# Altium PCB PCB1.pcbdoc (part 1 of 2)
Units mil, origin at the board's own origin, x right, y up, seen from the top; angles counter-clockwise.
Board outline 3270 x 3720 mil, 2 copper layers (Top Layer, Bottom Layer); 54 components, 39 nets, 206 pads, 56 vias.
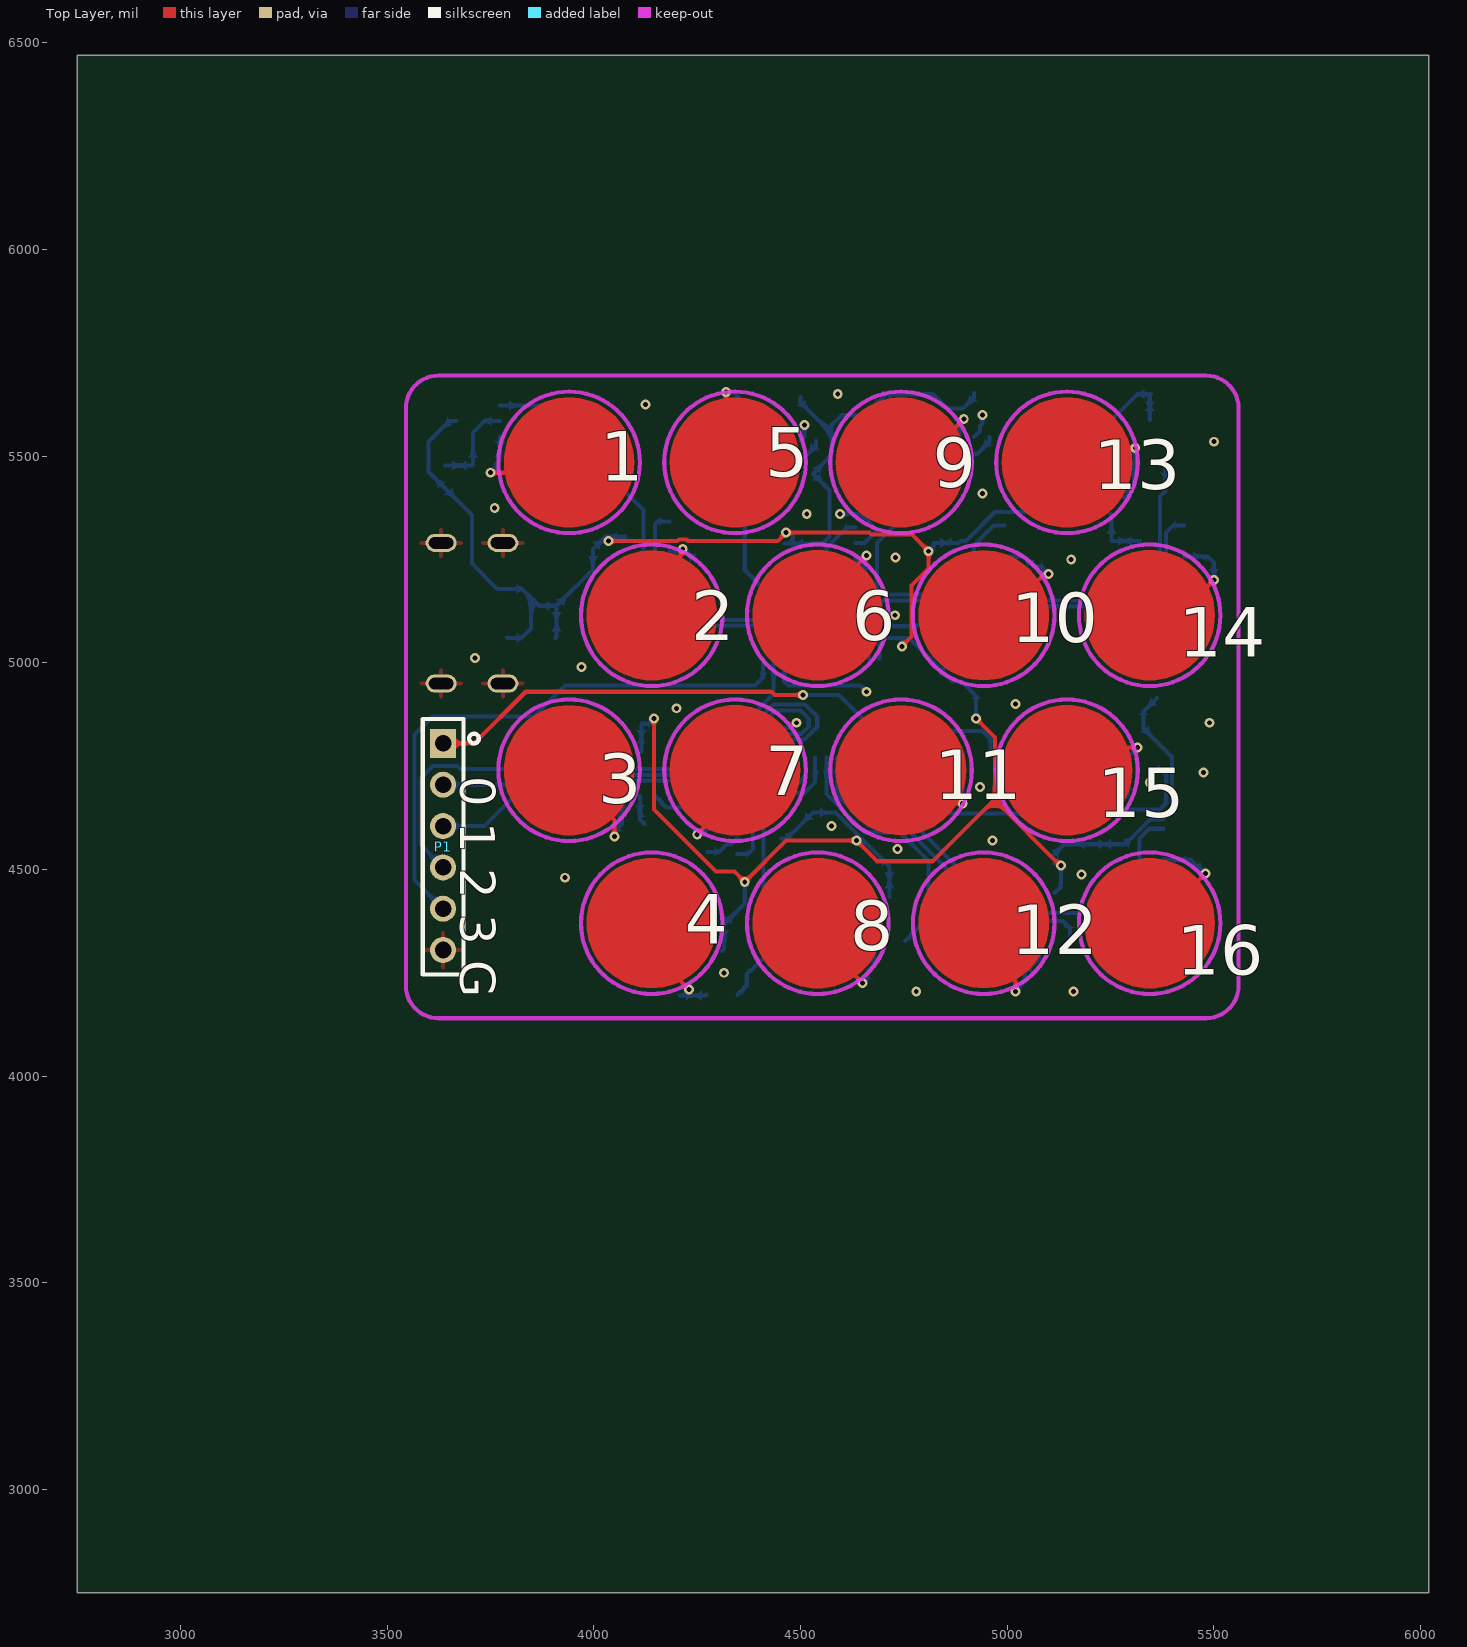
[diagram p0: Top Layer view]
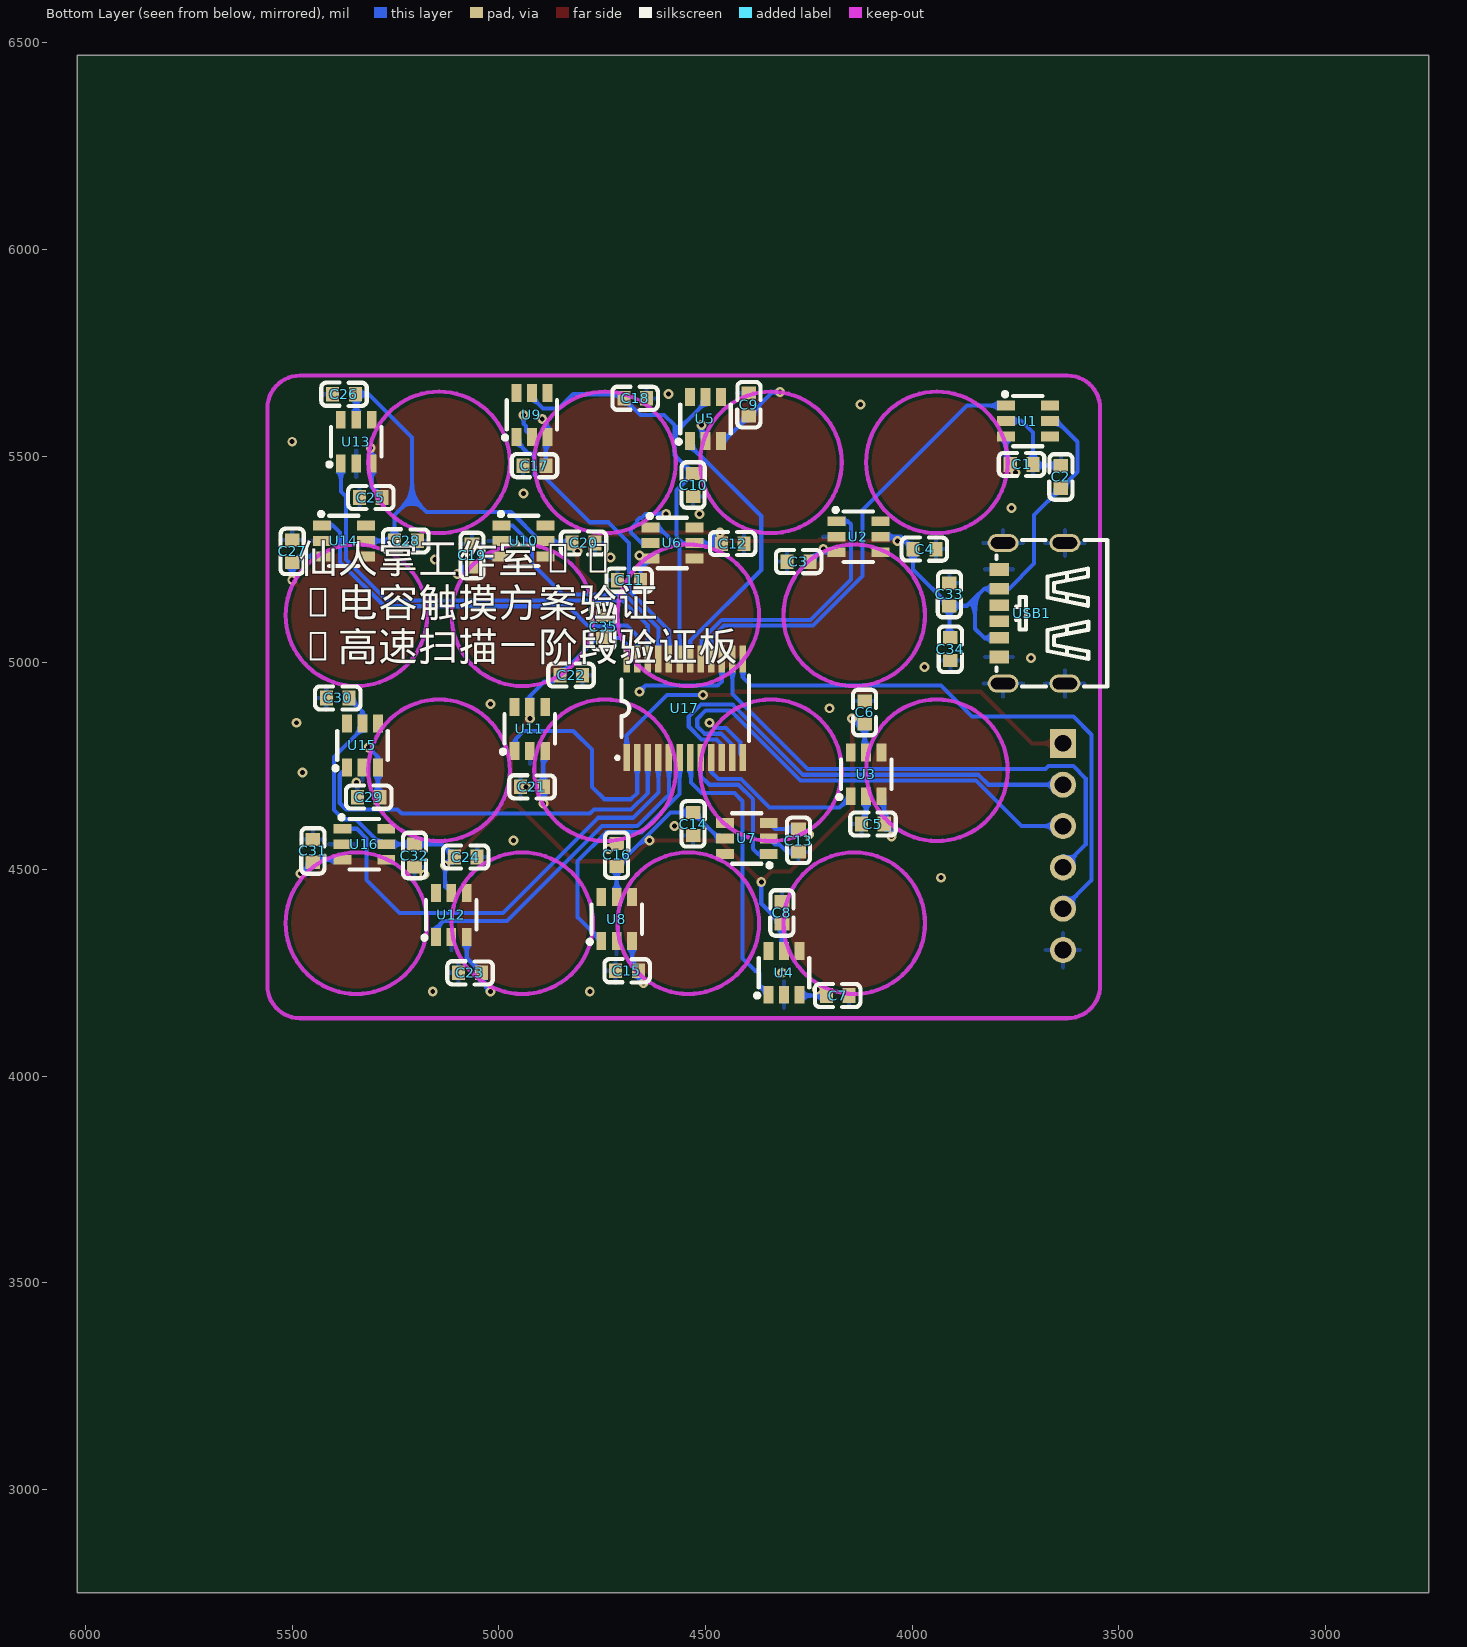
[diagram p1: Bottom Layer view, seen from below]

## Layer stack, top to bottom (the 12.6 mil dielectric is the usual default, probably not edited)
Top Layer: signal copper (thickness not stored)
Dielectric: dielectric 12.6, FR-4, Dk 4.8
Bottom Layer: signal copper (thickness not stored)

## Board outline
6020,2750 2750,2750 2750,6470 6020,6470

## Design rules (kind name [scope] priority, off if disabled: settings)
Clearance copperThickness1oz [All] p1: gap=7 ignorepadtopadclearanceinfootprint=FALSE except(4: Track-Track; 6: Track-SMDPad SMDPad-SMDPad Track-THPad SMDPad-THPad THPad-THPad Track-Via SMDPad-Via THPad-Via Via-Via SMDPad-Fill THPad-Fill Via-Fill Fill-Fill Track-Region SMDPad-Region THPad-Region Via-Region Region-Region Track-Poly SMDPad-Poly THPad-Poly Via-Poly Fill-Poly Region-Poly Poly-Poly Track-Text SMDPad-Text THPad-Text Via-Text Fill-Text Region-Text Poly-Text Text-Text; 6.9: Track-Hole SMDPad-Hole THPad-Hole Via-Hole Fill-Hole Region-Hole Poly-Hole Text-Hole Sheet-Hole; 11.8: Track-Fill Fill-Region Track-Sheet SMDPad-Sheet THPad-Sheet Via-Sheet Fill-Sheet Region-Sheet Poly-Sheet Text-Sheet)
Clearance copperThickness2oz [All] p1: gap=7 ignorepadtopadclearanceinfootprint=FALSE except(6: Track-SMDPad SMDPad-SMDPad Track-THPad SMDPad-THPad THPad-THPad Track-Via SMDPad-Via THPad-Via Via-Via SMDPad-Fill THPad-Fill Via-Fill Fill-Fill Track-Region SMDPad-Region THPad-Region Via-Region Region-Region Track-Poly SMDPad-Poly THPad-Poly Via-Poly Fill-Poly Region-Poly Poly-Poly Track-Text SMDPad-Text THPad-Text Via-Text Fill-Text Region-Text Poly-Text Text-Text; 6.9: Track-Hole SMDPad-Hole THPad-Hole Via-Hole Fill-Hole Region-Hole Poly-Hole Text-Hole Sheet-Hole; 8: Track-Track; 11.8: Track-Fill Fill-Region Track-Sheet SMDPad-Sheet THPad-Sheet Via-Sheet Fill-Sheet Region-Sheet Poly-Sheet Text-Sheet)
DiffPairsRouting differentialPair [All] p1: maxuncoupledlength=10 maxlimit=6 mostfreqgap=6 toplayer_minwidth=5 toplayer_prefwidth=10 toplayer_maxwidth=100 bottomlayer_minwidth=5 bottomlayer_prefwidth=10 bottomlayer_maxwidth=100
PasteMaskExpansion pasteMaskExpansion [All] p1:
PlaneConnect innerPlane [All] p1: planeconnectstyle=Relief reliefexpansion=20 reliefentries=4 reliefconductorwidth=10 reliefairgap=10
PolygonConnect copperRegion [All] p1: connectstyle=Relief reliefentries=4 reliefconductorwidth=10 polygonreliefangle="90 Angle" airgapwidth=10
RoutingVias viaSize [All] p1: viastyle="Through Hole" holewidth=12.0078 minholewidth=11.811 maxholewidth=248.0314 width=24.0158 minwidth=19.685 maxwidth=393.7008
SolderMaskExpansion solderMaskExpansion [All] p1: useseparateexpansions=TRUE expansion=2 expansionbottom=2
Width copperThickness1oz [All] p1: maxlimit=100 minlimit=5 preferedwidth=10
Width copperThickness2oz [All] p1: maxlimit=100 minlimit=8 preferedwidth=10

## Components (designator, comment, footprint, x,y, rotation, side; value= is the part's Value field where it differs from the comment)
C1 "CL10C120JB8NNNC" C0603 3735,5480 r180 bottom
C2 "CC0603KRX7R9BB104" C0603 3640,5450 r90 bottom
C3 "CL10C120JB8NNNC" C0603 4275,5245 r0 bottom
C4 "CC0603KRX7R9BB104" C0603 3970,5275 r180 bottom
C5 "CL10C120JB8NNNC" C0603 4095,4610 r0 bottom
C6 "CC0603KRX7R9BB104" C0603 4115,4880 r90 bottom
C7 "CL10C120JB8NNNC" C0603 4180,4195 r180 bottom
C8 "CC0603KRX7R9BB104" C0603 4315,4395 r90 bottom
C9 "CL10C120JB8NNNC" C0603 4395,5625 r90 bottom
C10 "CC0603KRX7R9BB104" C0603 4530,5430 r270 bottom
C11 "CL10C120JB8NNNC" C0603 4685,5200 r0 bottom
C12 "CC0603KRX7R9BB104" C0603 4434.1,5288.47 r180 bottom
C13 "CL10C120JB8NNNC" C0603 4275,4570 r270 bottom
C14 "CC0603KRX7R9BB104" C0603 4530,4610 r270 bottom
C15 "CL10C120JB8NNNC" C0603 4690,4255 r0 bottom
C16 "CC0603KRX7R9BB104" C0603 4715,4535 r90 bottom
C17 "CL10C120JB8NNNC" C0603 4913.96,5477.13 r0 bottom
C18 "CC0603KRX7R9BB104" C0603 4670,5640 r180 bottom
C19 "CL10C120JB8NNNC" C0603 5065,5260 r90 bottom
C20 "CC0603KRX7R9BB104" C0603 4795,5290 r180 bottom
C21 "CL10C120JB8NNNC" C0603 4920,4700 r0 bottom
C22 "CC0603KRX7R9BB104" C0603 4825,4970 r180 bottom
C23 "CL10C120JB8NNNC" C0603 5070,4250 r0 bottom
C24 "CC0603KRX7R9BB104" C0603 5080,4530 r180 bottom
C25 "CL10C120JB8NNNC" C0603 5310,5400 r0 bottom
C26 "CC0603KRX7R9BB104" C0603 5375,5650 r0 bottom
C27 "CL10C120JB8NNNC" C0603 5500,5270 r90 bottom
C28 "CC0603KRX7R9BB104" C0603 5225,5295 r180 bottom
C29 "CL10C120JB8NNNC" C0603 5315,4675 r0 bottom
C30 "CC0603KRX7R9BB104" C0603 5390,4915 r0 bottom
C31 "CL10C120JB8NNNC" C0603 5450,4545 r90 bottom
C32 "CC0603KRX7R9BB104" C0603 5204.22,4533.59 r270 bottom
C33 "CC0603KRX7R9BB104" C0603 3909.79,5165.61 r90 bottom
C34 "CL10A106KP8NNNC" C0603 3907.35,5033.17 r90 bottom
C35 "CC0603KRX7R9BB104" C0603 4747.62,5087.54 r90 bottom
P1 "2.54-1*6P母" hdr-th_6p-p2.54-v-f 3635,4555 r270 top
U1 "TTP223E-HA6" SOT-23-6_L2.9-W1.6-P0.95-LS2.8-BR 3720,5585 r0 bottom
U2 "TTP223E-HA6" SOT-23-6_L2.9-W1.6-P0.95-LS2.8-BR 4130,5305 r0 bottom
U3 "TTP223E-HA6" SOT-23-6_L2.9-W1.6-P0.95-LS2.8-BR 4111.3,4730.21 r270 bottom
U4 "TTP223E-HA6" SOT-23-6_L2.9-W1.6-P0.95-LS2.8-BR 4310,4250 r270 bottom
U5 "TTP223E-HA6" SOT-23-6_L2.9-W1.6-P0.95-LS2.8-BR 4500,5590 r270 bottom
U6 "TTP223E-HA6" SOT-23-6_L2.9-W1.6-P0.95-LS2.8-BR 4580,5290 r0 bottom
U7 "TTP223E-HA6" SOT-23-6_L2.9-W1.6-P0.95-LS2.8-BR 4400,4575 r180 bottom
U8 "TTP223E-HA6" SOT-23-6_L2.9-W1.6-P0.95-LS2.8-BR 4715,4380 r270 bottom
U9 "TTP223E-HA6" SOT-23-6_L2.9-W1.6-P0.95-LS2.8-BR 4920,5600 r270 bottom
U10 "TTP223E-HA6" SOT-23-6_L2.9-W1.6-P0.95-LS2.8-BR 4940,5295 r0 bottom
U11 "TTP223E-HA6" SOT-23-6_L2.9-W1.6-P0.95-LS2.8-BR 4925,4840 r270 bottom
U12 "TTP223E-HA6" SOT-23-6_L2.9-W1.6-P0.95-LS2.8-BR 5115,4390 r270 bottom
U13 "TTP223E-HA6" SOT-23-6_L2.9-W1.6-P0.95-LS2.8-BR 5345,5535 r270 bottom
U14 "TTP223E-HA6" SOT-23-6_L2.9-W1.6-P0.95-LS2.8-BR 5375,5295 r0 bottom
U15 "TTP223E-HA6" SOT-23-6_L2.9-W1.6-P0.95-LS2.8-BR 5330,4800 r270 bottom
U16 "TTP223E-HA6" SOT-23-6_L2.9-W1.6-P0.95-LS2.8-BR 5325.54,4561.15 r0 bottom
U17 "74HC4067PW/C2118" TSSOP-24_L7.8-W4.4-P0.65-LS6.4-BL 4550,4890 r180 bottom
USB1 "TYPE-C 6P" TYPE-C-SMD_TYPE-C-6P 3710,5120 r90 bottom

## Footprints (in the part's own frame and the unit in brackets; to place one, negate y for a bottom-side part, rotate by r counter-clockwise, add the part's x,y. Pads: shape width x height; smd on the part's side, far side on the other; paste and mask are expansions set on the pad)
C0603 [mm]
  rect 0.8x0.9 smd: 1(-0.7,0) 2(0.7,0)
  silkscreen extent -1.41,-0.71 1.39,0.72
hdr-th_6p-p2.54-v-f [mm]
  rect 1.8x1.6 hole 1.02: 1(-6.35,0)
  round 1.6 hole 1.02: 2(-3.81,0) 3(-1.27,0) 4(1.27,0) 5(3.81,0) 6(6.35,0)
  silkscreen extent -7.85,-1.25 7.85,2.2
SOT-23-6_L2.9-W1.6-P0.95-LS2.8-BR [mm]
  rect 1.1x0.6 smd: 1(1.35,-0.95) 2(1.35,0) 3(1.35,0.95) 4(-1.35,0.95) 5(-1.35,0) 6(-1.35,-0.95)
  silkscreen extent -0.9,-1.78 1.52,1.55
TSSOP-24_L7.8-W4.4-P0.65-LS6.4-BL [mm]
  rect 0.4x1.65 smd: 1(-3.575,-3.023) 2(-2.925,-3.023) 3(-2.275,-3.023) 4(-1.625,-3.023) 5(-0.975,-3.023) 6(-0.325,-3.023) 7(0.325,-3.023) 8(0.975,-3.023) 9(1.625,-3.023) 10(2.275,-3.023) 11(2.925,-3.023) 12(3.575,-3.023) 13(3.575,3.023) 14(2.925,3.023) 15(2.275,3.023) 16(1.625,3.023) 17(0.975,3.023) 18(0.325,3.023) 19(-0.325,3.023) 20(-0.975,3.023) 21(-1.625,3.023) 22(-2.275,3.023) 23(-2.925,3.023) 24(-3.575,3.023)
  silkscreen extent -4.24,-3.15 3.94,2.01
TYPE-C-SMD_TYPE-C-6P [mm]
  oval 1.1x1.9 hole 0.7 slot 1.5 at 90 deg: 7(-4.32,-2.025) 7(-4.32,1.775) 7(4.32,-2.025) 7(4.32,1.775)
  rect 0.7x1.2 smd: A5(-0.5,2.025) A9(1.5,2.025) B5(0.5,2.025) B9(-1.5,2.025)
  rect 0.8x1.2 smd: A12(2.7,2.025) B12(-2.7,2.025)
  silkscreen extent -4.5,-4.63 4.5,2.18

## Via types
v1: diameter 24.02, hole 12.01, Top Layer to Bottom Layer, 56 vias

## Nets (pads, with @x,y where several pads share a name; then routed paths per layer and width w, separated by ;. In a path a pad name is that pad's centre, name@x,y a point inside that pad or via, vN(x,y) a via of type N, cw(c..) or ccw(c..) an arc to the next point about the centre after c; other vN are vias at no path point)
+5V: C2.1 C4.1 C6.1 C8.1 C10.1 C12.1 C14.1 C16.1 C18.1 C20.1 C22.1 C24.1 C26.1 C28.1 C30.1 C32.1 C33.1 C34.2 C35.1 U1.5 U2.5 U3.5 U4.5 U5.5 U6.5 U7.5 U8.5 U9.5 U10.5 U11.5 U12.5 U13.5 U14.5 U15.5 U16.5 U17.24 USB1.A9 USB1.B9 | length 7845.7
  Top Layer w10: v1(4035,5295) 4202.48,5295 4205.48,5297.99 4224.52,5297.99 4227.52,5295 4445,5295 v1(4465,5315) 4666.66,5315 4670.96,5310.71 4769.29,5310.71 v1(4810,5270) 4810,5228.34 4768.86,5187.19 4768.86,5063.86 v1(4745,5040) ; v1(4145,4865) 4145,4645 4295,4495 4340,4495 v1(4365,4470) 4465,4570 v1(4635,4570) 4685,4520 4820,4520 4967.81,4667.81 4970.43,4667.81 ; v1(4925,4865) 4970.43,4819.57 4970.43,4667.81 ; v1(5130,4510) 5128.24,4510 4970.43,4667.81
  Bottom Layer w10: U1.5@3666.85,5585 3650,5585 3600,5535 3600,5462.44 C2.1@3640,5422.44 3705,5357.44 3705,5240 3765.95,5179.06 USB1.A9@3789.72,5179.06 3825.95,5179.06 3847.5,5157.5 ; USB1.B9@3789.72,5060.94 3790.67,5060 3825,5060 3847.5,5082.5 3847.5,5157.5 ; C34.2@3907.35,5060.73 3909.79,5063.17 C33.1@3909.79,5138.05 ; v1(4035,5295) 4035,5297.56 4027.56,5305 ; U2.5@4076.85,5305 4027.56,5305 ; U3.5@4111.3,4783.36 4115,4787.07 C6.1@4115,4852.44 4132.44,4852.44 v1(4145,4865) ; U4.5@4310,4303.15 4315,4308.15 C8.1@4315,4367.44 4365,4417.44 v1(4365,4470) ; U7.5@4453.15,4575 4467.44,4575 C14.1@4530,4637.56 4584.88,4637.56 4652.44,4570 ; C12.1@4461.66,5288.47 C12.1@4471.72,5288.47 ; v1(4465,5315) 4474.74,5315 4481.62,5308.11 4481.62,5298.38 C12.1@4471.72,5288.47 ; U5.5@4500,5643.15 4500,5630 4575,5555 ; v1(4635,4570) 4652.44,4570 ; U17.24@4690.74,5009 4690.74,5045.74 4704.98,5059.98 C35.1@4747.62,5059.98 ; U8.5@4715,4433.15 C16.1@4715,4507.44 4652.44,4570 ; v1(4745,5040) 4745,5057.36 C35.1@4747.62,5059.98 ; v1(4810,5270) 4822.56,5282.56 C20.1@4822.56,5290 4881.85,5290 U10.5@4886.85,5295 4900,5295 4970,5365 5175,5365 5210,5400 ; U9.5@4920,5653.15 4920,5641.55 4893.45,5615 4855,5615 4820,5650 4707.56,5650 C18.1@4697.56,5640 4657.56,5600 4600,5600 4575,5575 4575,5555 ; v1(4925,4865) U11.5@4925,4893.15 4925,4920 4890,4955 4867.56,4955 C22.1@4852.56,4970 4762.58,5059.98 C35.1@4747.62,5059.98 ; U12.5@5115,4443.15 5129.6,4457.75 5129.6,4469.35 5130,4469.75 v1(5130,4510) 5127.56,4510 C24.1@5107.56,4530 5138.71,4561.15 C32.1@5204.22,4561.15 U16.5@5272.39,4561.15 5286.15,4561.15 5345.98,4620.98 5352.12,4620.98 5352.48,4621.35 5376.35,4621.35 5399.02,4644.02 5399.02,4772.54 5330,4841.55 U15.5@5330,4853.15 5330,4882.56 C30.1@5362.44,4915 ; U14.5@5321.85,5295 C28.1@5252.56,5295 5252.56,5357.44 5210,5400 ; U13.5@5345,5588.15 5345,5647.56 C26.1@5347.44,5650 5315,5650 5210,5545 5210,5400 ; 3847.5,5157.5 3866.95,5138.05 C33.1@3909.79,5138.05 ; C33.1@3909.79,5138.05 3997.56,5225.82 C4.1@3997.56,5275 4027.56,5305 ; C12.1@4471.72,5288.47 4525.32,5288.47 U6.5@4526.85,5290 4555,5290 4570,5305 4570,5417.56 C10.1@4530,5457.56 4575,5502.56 4575,5555
GND: C1.2 C2.2 C3.2 C4.2 C5.2 C6.2 C7.2 C8.2 C9.2 C10.2 C11.2 C12.2 C13.2 C14.2 C15.2 C16.2 C17.2 C18.2 C19.2 C20.2 C21.2 C22.2 C23.2 C24.2 C25.2 C26.2 C27.2 C28.2 C29.2 C30.2 C31.2 C32.2 C33.2 C34.1 C35.2 P1.6 U1.2 U2.2 U3.2 U4.2 U5.2 U6.2 U7.2 U8.2 U9.2 U10.2 U11.2 U12.2 U13.2 U14.2 U15.2 U16.2 U17.12 U17.15 USB1.7 USB1.A12 USB1.B12 | length 1050.4
  Bottom Layer w10: C2.2@3640,5477.56 3705,5477.56 C1.2@3707.44,5480 3707.44,5557.44 3735,5585 U1.2@3773.15,5585 ; U3.2@4111.3,4677.06 4111.3,4621.27 C5.2@4122.56,4610 ; C13.2@4275,4542.44 4302.69,4542.44 4320.65,4560.4 4332.25,4560.4 U7.2@4346.85,4575 ; U17.12@4409.26,4771 4409.26,4774.26 4415.98,4780.98 4415.98,4808.03 4450.45,4842.5 4477.5,4842.5 v1(4490,4855) ; U17.15@4460.43,5009 4460.43,4955 4470.43,4945 4645,4945 v1(4660,4930) ; U5.2@4500,5536.85 4510,5546.85 v1(4510,5575) ; v1(4595,5360) 4645,5360 4654.8,5350.2 4659.35,5350.2 4665.79,5343.76 4665.79,5339.21 4680,5325 4680,5315 4655,5290 U6.2@4633.15,5290 ; U9.2@4920,5546.85 4934.6,5561.45 4934.6,5573.05 4940,5578.45 v1(4940,5600)
  other v1: 4780,4205 5160,4205 4314.49,4250 3930,4480 5179.86,4487.49 4735,4550 4965,4570 4575,4605 4933.97,4699.89 5345,4710 5475,4735 5490,4855 4200,4890 5020,4900 3970,4990 3712.13,5011.73 4728.52,5115.1 5155,5250 4730,5255 4515,5360 3760,5375 4940,5410 5500,5535 4125,5625 4590,5650
OUT: P1.1 U17.1 | length 1204.6
  Top Layer w10: P1.1@3635,4805 3710,4805 3835,4930 4430,4930 4437.99,4922.01 v1(4506.26,4922.01)
  Bottom Layer w10: v1(4506.26,4922.01) 4592.99,4922.01 4690.74,4824.26 U17.1@4690.74,4771
PAD1: 
PAD2: C3.1 U2.3 | length 122.4
  Top Layer w10: 4195,5245 4215,5265 v1(4215,5275)
  Bottom Layer w10: U2.3@4183.15,5267.6 v1@4207.6,5267.6 ; v1(4215,5275) v1@4207.6,5267.6 ; C3.1@4247.44,5245 4224.84,5267.6 v1@4207.6,5267.6
PAD3: C5.1 U3.3 | length 168.2
  Top Layer w10: 4035,4635 4050,4620 v1(4050,4580)
  Bottom Layer w10: v1(4050,4580) 4050,4592.56 C5.1@4067.44,4610 4067.44,4670.61 U3.3@4073.89,4677.06
PAD4: C7.1 U4.3 | length 160.7
  Top Layer w10: 4185,4265 4185,4255 v1(4230,4210)
  Bottom Layer w10: C7.1@4207.56,4195 C7.1@4215,4195 ; v1(4230,4210) C7.1@4215,4195 ; U4.3@4272.6,4196.85 4270.75,4195 C7.1@4215,4195
PAD5: C9.1 U5.3 | length 263.1
  Top Layer w10: v1(4320,5655) 4320,5640 4360,5600
  Bottom Layer w10: v1(4320,5655) 4337.44,5655 C9.1@4395,5597.44 4455.59,5536.85 U5.3@4462.6,5536.85
PAD6: C11.1 U6.3 | length 142.9
  Top Layer w10: 4635,5220 4635,5235 v1(4660,5260)
  Bottom Layer w10: C11.1@4657.44,5200 4657.44,5228.31 U6.3@4633.15,5252.6 4652.6,5252.6 v1(4660,5260)
PAD7: C13.1 U7.3 | length 158.6
  Top Layer w10: v1(4250,4585) 4275,4610 4275,4625
  Bottom Layer w10: v1(4250,4585) 4262.44,4585 C13.1@4275,4597.56 4320.41,4597.56 4320.65,4597.8 4332.25,4597.8 U7.3@4346.85,4612.4
PAD8: C15.1 U8.3 | length 218.1
  Top Layer w10: 4590,4305 4590,4285 v1(4650,4225)
  Bottom Layer w10: v1(4650,4225) 4662.44,4237.44 C15.1@4662.44,4255 4677.6,4270.16 U8.3@4677.6,4326.85
PAD9: C17.1 U9.3 | length 169.1
  Top Layer w10: 4860,5555 v1(4895,5590)
  Bottom Layer w10: C17.1@4886.4,5477.13 4886.4,5543.05 U9.3@4882.6,5546.85 4885,5549.25 4885,5580 v1(4895,5590)
PAD10: C19.1 U10.3 | length 205.2
  Top Layer w10: 5040,5165 5090,5215 v1(5100,5215)
  Bottom Layer w10: U10.3@4993.15,5257.6 5039.84,5257.6 C19.1@5065,5232.44 5082.56,5232.44 v1(5100,5215)
PAD11: C21.1 U11.3 | length 205.8
  Top Layer w10: 4830,4695 4865,4660 v1(4892.44,4660)
  Bottom Layer w10: U11.3@4887.6,4786.85 4892.44,4782.01 C21.1@4892.44,4700 v1(4892.44,4660)
PAD12: C23.1 U12.3 | length 230.2
  Top Layer w10: 4985,4265 5020,4230 v1(5020,4205)
  Bottom Layer w10: v1(5020,4205) 5042.44,4227.44 C23.1@5042.44,4250 5077.6,4285.16 U12.3@5077.6,4336.85
PAD13: C25.1 U13.3 | length 234.7
  Top Layer w10: 5215,5500 5235,5520 v1(5310,5520)
  Bottom Layer w10: C25.1@5282.44,5400 5307.6,5425.16 U13.3@5307.6,5481.85 5310,5484.25 v1(5310,5520)
PAD14: C27.1 U14.3 | length 191.8
  Top Layer w10: 5435,5185 5485,5185 v1(5500,5200)
  Bottom Layer w10: U14.3@5428.15,5257.6 5484.84,5257.6 C27.1@5500,5242.44 v1(5500,5200)
PAD15: C29.1 U15.3 | length 251.8
  Top Layer w10: 5205,4770 5230,4795 v1(5315,4795)
  Bottom Layer w10: C29.1@5287.44,4675 5292.6,4680.16 U15.3@5292.6,4746.85 5292.6,4772.6 v1(5315,4795)
PAD16: C31.1 U16.3 | length 157.7
  Top Layer w10: 5450,4460 v1(5480,4490)
  Bottom Layer w10: U16.3@5378.69,4523.75 5443.69,4523.75 C31.1@5450,4517.44 5477.44,4490 v1(5480,4490)
S0: P1.2 U17.10 | length 1150.7
  Bottom Layer w10: P1.2@3635,4705 3815.18,4705 3839.19,4729.02 4264.19,4729.02 4434.19,4899.02 4510.98,4899.02 4540.37,4869.63 4540.37,4845.37 4509.46,4814.46 4473.6,4814.46 4460.43,4801.3 U17.10@4460.43,4771
S1: P1.3 U17.11 | length 1162
  Bottom Layer w10: P1.3@3635,4605 3735,4605 3845,4715 4270,4715 4440,4885 4499.5,4885 4520,4864.5 4520,4845.93 4502.55,4828.48 4462.02,4828.48 4434.84,4801.3 U17.11@4434.84,4771
S2: P1.4 U17.14 | length 1267.4
  Bottom Layer w10: P1.4@3635,4505 3580,4560 3580,4720 3610,4750 3670,4750 3676.97,4743.03 4253.03,4743.03 4434.84,4924.84 U17.14@4434.84,5009
S3: P1.5 U17.13 | length 1394.9
  Bottom Layer w10: P1.5@3635,4405 3565.98,4474.02 3565.98,4825.98 3610,4870 3855,4870 3930,4945 4390,4945 4409.26,4964.26 U17.13@4409.26,5009
T1: U1.1 U17.16 | length 1090
  Bottom Layer w10: U1.1@3773.15,5622.4 3867.6,5622.4 4120,5370 4120,5210 4240,5090 4455,5090 4486.02,5058.98 U17.16@4486.02,5009
T2: U2.1 U17.17 | length 641.1
  Bottom Layer w10: U2.1@4183.15,5342.4 4155,5342.4 4147.93,5335.33 4147.93,5201.89 4245.81,5104.02 4460.81,5104.02 4509.82,5055 4509.82,5010.79 U17.17@4511.61,5009
T3: U3.1 U17.9 | length 419.1
  Bottom Layer w10: U3.1@4148.69,4677.06 4175.76,4650 4345.18,4650 4414.19,4719.02 4469.02,4719.02 4486.02,4736.02 U17.9@4486.02,4771
T4: U4.1 U17.7 | length 700.4
  Bottom Layer w10: U4.1@4347.4,4196.85 4370,4219.45 4370,4247.93 4377.07,4255 4380,4255 4410,4285 4410,4665 4430,4685 4510,4685 4535,4710 U17.7@4535,4771
T5: U5.1 U17.18 | length 671.9
  Bottom Layer w10: U17.18@4537.21,5009 4537.21,5052.79 4365,5225 4365,5355 4514.21,5504.21 4516.36,5504.21 4537.4,5525.25 U5.1@4537.4,5536.85
T6: U6.1 U17.19 | length 359.8
  Bottom Layer w10: U17.19@4562.79,5009 4562.79,5277.97 4612.22,5327.4 U6.1@4633.15,5327.4
T7: U7.1 U17.8 | length 357.7
  Bottom Layer w10: U7.1@4346.85,4537.6 4372.6,4537.6 4385,4550 4385,4670 4420,4705 4490,4705 4511.61,4726.61 U17.8@4511.61,4771
T8: U8.1 U17.6 | length 620.2
  Bottom Layer w10: U17.6@4562.79,4771 4562.79,4682.21 4655,4590 4740,4590 4810,4520 4810,4384.45 U8.1@4752.4,4326.85
T9: U9.1 U17.20 | length 731.7
  Bottom Layer w10: U17.20@4588.38,5009 4588.38,5078.38 4685,5175 4685,5290 4735,5340 4779.79,5340 4888.22,5448.43 4906.7,5448.43 4913.13,5454.86 4913.13,5473.34 4914.79,5475 4914.79,5499.4 4921.22,5505.83 4927.98,5505.83 4957.4,5535.25 U9.1@4957.4,5546.85
T10: U10.1 U17.21 | length 583.9
  Bottom Layer w10: U17.21@4613.97,5009 4613.97,5084.15 4694.82,5165 4845,5165 4920,5240 4920,5250 4919.49,5250.51 4919.49,5284.49 4967.4,5332.4 U10.1@4993.15,5332.4
T11: U11.1 U17.2 | length 545.7
  Bottom Layer w10: U17.2@4665,4771 4665,4685 4680,4670 4745,4670 4775,4700 4775,4790 4820,4835 4940,4835 4960,4815 4960,4789.25 U11.1@4962.4,4786.85
T12: U12.1 U17.5 | length 808.4
  Bottom Layer w10: U17.5@4588.38,4771 4588.38,4681.62 4665,4605 4750,4605 4980,4375 5135,4375 5152.4,4357.6 U12.1@5152.4,4336.85
T13: U13.1 U17.22 | length 1114.7
  Bottom Layer w10: U17.22@4639.56,5009 4639.56,5089.92 4700.63,5150.98 5270.98,5150.98 5370,5250 5370,5402.06 5382.4,5414.46 U13.1@5382.4,5481.85
T14: U14.1 U17.23 | length 972.8
  Bottom Layer w10: U17.23@4665.15,5009 4665.15,5054.85 4665,5055 4665,5065 4690,5090 4723.72,5090 4725.35,5088.37 4769.88,5088.37 4771.51,5090 4785,5090 4831.97,5136.97 5276.79,5136.97 5384.02,5244.19 5384.02,5315 5401.42,5332.4 U14.1@5428.15,5332.4
T15: U15.1 U17.3 | length 956
  Bottom Layer w10: U17.3@4639.56,4771 4639.56,4685.44 4680,4645 4770,4645 4780,4635 5235,4635 5245,4645 5369.27,4645 5385,4660.73 5385,4729.25 U15.1@5367.4,4746.85
T16: U16.1 U17.4 | length 1113.1
  Bottom Layer w10: U17.4@4613.97,4771 4613.97,4686.03 4675,4625 4760,4625 4990,4395 5240,4395 5320,4475 5320,4575 5343.55,4598.55 U16.1@5378.69,4598.55
pads on no net: C1.1 U1.3 U1.4 U1.6 U2.4 U2.6 U3.4 U3.6 U4.4 U4.6 U5.4 U5.6 U6.4 U6.6 U7.4 U7.6 U8.4 U8.6 U9.4 U9.6 U10.4 U10.6 U11.4 U11.6 U12.4 U12.6 U13.4 U13.6 U14.4 U14.6 U15.4 U15.6 U16.4 U16.6 USB1.A5 USB1.B5
copper on no net: | length 142.2
  Top Layer w10: v1(3750,5460) 3795,5460
  Bottom Layer w10: v1(3750,5460) 3762.56,5472.56 3762.56,5480 3773.15,5490.59 3773.15,5547.6

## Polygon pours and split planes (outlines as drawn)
GND on Bottom Layer (solid, remove dead copper, pour order 2): 3345,3900 5770,3900 5770,5870 3345,5870
GND on Top Layer (solid, remove dead copper): 3000,3000 5635,3000 5635,6220 3000,6220

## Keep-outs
Board Outline Layer:
  lines w10: 3545,4218.74 ccw(c3623.74,4218.74) 3623.74,4140 5481.26,4140 ccw(c5481.26,4218.74) 5560,4218.74 5560,5616.26 ccw(c5481.26,5616.26) 5481.26,5695 3623.74,5695 ccw(c3623.74,5616.26) 3545,5616.26 3545,4218.74
Multi-Layer:
  circle w10: c3940,5485 r171.26
  circle w10: c4341.57,5485 r171.26
  circle w10: c4140,5115 r171.26
  circle w10: c3940,4740 r171.26
  circle w10: c4341.57,4740 r171.26
  circle w10: c4140,4370 r171.26
  circle w10: c4541.57,4370 r171.26
  circle w10: c4943.15,4370 r171.26
  circle w10: c5344.72,4370 r171.26
  circle w10: c5144.72,4740 r171.26
  circle w10: c4743.15,4740 r171.26
  circle w10: c4541.57,5115 r171.26
  circle w10: c4943.15,5115 r171.26
  circle w10: c5344.72,5115 r171.26
  circle w10: c5144.72,5485 r171.26
  circle w10: c4743.15,5485 r171.26

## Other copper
Top Layer:
  region: 4097.48,5485 ccw(c3940,5484.78) 3782.52,5485 ccw(c3940,5485.22)
  region net PAD5: 4499.06,5485 ccw(c4341.57,5485) 4184.09,5485 ccw(c4341.57,5485)
  region net PAD9: 4900.63,5485 ccw(c4743.15,5484.67) 4585.67,5485 ccw(c4743.15,5485.33)
  region net PAD13: 5302.2,5485 ccw(c5144.72,5485) 4987.24,5485 ccw(c5144.72,5485)
  region net PAD2: 4297.48,5115 ccw(c4140,5114.78) 3982.52,5115 ccw(c4140,5115.22)
  region net PAD6: 4699.06,5115 ccw(c4541.57,5115) 4384.09,5115 ccw(c4541.57,5115)
  region net PAD10: 5100.63,5115 ccw(c4943.15,5114.67) 4785.67,5115 ccw(c4943.15,5115.33)
  region net PAD14: 5502.2,5115 ccw(c5344.72,5115) 5187.24,5115 ccw(c5344.72,5115)
  region net PAD3: 4097.48,4740 ccw(c3940,4739.78) 3782.52,4740 ccw(c3940,4740.22)
  region net PAD7: 4499.06,4740 ccw(c4341.57,4740) 4184.09,4740 ccw(c4341.57,4740)
  region net PAD11: 4900.63,4740 ccw(c4743.15,4739.67) 4585.67,4740 ccw(c4743.15,4740.33)
  region net PAD15: 5302.2,4740 ccw(c5144.72,4740) 4987.24,4740 ccw(c5144.72,4740)
  region net PAD4: 4297.48,4370 ccw(c4140,4369.78) 3982.52,4370 ccw(c4140,4370.22)
  region net PAD8: 4699.06,4370 ccw(c4541.57,4370) 4384.09,4370 ccw(c4541.57,4370)
  region net PAD12: 5100.63,4370 ccw(c4943.15,4369.67) 4785.67,4370 ccw(c4943.15,4370.33)
  region net PAD16: 5502.2,4370 ccw(c5344.72,4370) 5187.24,4370 ccw(c5344.72,4370)
  region net OUT: 3681.5,4810 3681.5,4800 ccw(c3681.5,4781.25) 3666.5,4792.5 3666.5,4817.5 ccw(c3681.5,4828.75)
  region: 3766.41,5465 3766.41,5455 3765.29,5454.91 3764.16,5454.66 3761.93,5453.77 3759.83,5452.5 3758.01,5451.05 3758.01,5468.95 3759.83,5467.5 3761.93,5466.23 3764.16,5465.34 3765.29,5465.09
  region net PAD2: 4212.59,5255.52 4202.15,5259.22 4204.09,5261.31 4204.91,5262.38 4205.55,5263.47 4205.95,5264.58 4206.07,5265.72 4205.84,5266.87 4205.22,5268.04 4222.66,5265.76 4220.21,5263.5 4217.54,5260.74
  region net PAD3: 4045,4596.41 4055,4596.41 4055.09,4595.29 4055.34,4594.16 4056.23,4591.93 4057.5,4589.83 4058.95,4588.01 4041.05,4588.01 4042.5,4589.83 4043.77,4591.93 4044.66,4594.16 4044.91,4595.29
  region net PAD4: 4214.86,4218.07 4221.93,4225.14 4222.79,4224.41 4223.76,4223.79 4225.98,4222.84 4228.35,4222.26 4230.67,4221.99 4218.01,4209.33 4217.74,4211.65 4217.16,4214.02 4216.21,4216.24 4215.59,4217.21
  region net PAD5: 4325,5640 4315,5640 4314.91,5641.06 4314.66,5642.03 4313.77,5643.78 4312.5,5645.39 4311.05,5646.99 4328.95,5646.99 4327.5,5645.39 4326.23,5643.78 4325.34,5642.03 4325.09,5641.06
  region net PAD6: 4651.93,5244.86 4644.86,5251.93 4645.59,5252.79 4646.21,5253.76 4647.16,5255.98 4647.74,5258.35 4648.01,5260.67 4660.67,5248.01 4658.35,5247.74 4655.98,5247.16 4653.76,5246.21 4652.79,5245.59
  region net PAD7: 4258.07,4600.14 4265.14,4593.07 4264.41,4592.21 4263.79,4591.24 4262.84,4589.02 4262.26,4586.65 4261.99,4584.33 4249.33,4596.99 4251.65,4597.26 4254.02,4597.84 4256.24,4598.79 4257.21,4599.41
  region net PAD8: 4634.86,4233.07 4641.93,4240.14 4642.79,4239.41 4643.76,4238.79 4645.98,4237.84 4648.35,4237.26 4650.67,4236.99 4638.01,4224.33 4637.74,4226.65 4637.16,4229.02 4636.21,4231.24 4635.59,4232.21
  region net PAD9: 4886.93,5574.86 4879.86,5581.93 4880.59,5582.79 4881.21,5583.76 4882.16,5585.98 4882.74,5588.35 4883.01,5590.67 4895.67,5578.01 4893.35,5577.74 4890.98,5577.16 4888.76,5576.21 4887.79,5575.59
  region net PAD10: 5084.22,5202.15 5080.52,5212.59 5085.74,5217.54 5088.5,5220.21 5090.76,5222.66 5093.04,5205.22 5091.87,5205.84 5090.72,5206.07 5089.58,5205.95 5088.47,5205.55 5087.38,5204.91 5086.31,5204.09
  region net PAD11: 4876.03,4655 4876.03,4665 4877.15,4665.09 4878.28,4665.34 4880.51,4666.23 4882.61,4667.5 4884.43,4668.95 4884.43,4651.05 4882.61,4652.5 4880.51,4653.77 4878.28,4654.66 4877.15,4654.91
  region net PAD12: 5015,4221.41 5025,4221.41 5025.09,4220.29 5025.34,4219.16 5026.23,4216.93 5027.5,4214.83 5028.95,4213.01 5011.05,4213.01 5012.5,4214.83 5013.77,4216.93 5014.66,4219.16 5014.91,4220.29
  region net PAD13: 5293.59,5515 5293.59,5525 5294.71,5525.09 5295.84,5525.34 5298.07,5526.23 5300.17,5527.5 5301.99,5528.95 5301.99,5511.05 5300.17,5512.5 5298.07,5513.77 5295.84,5514.66 5294.71,5514.91
  region net PAD14: 5491.93,5184.86 5484.86,5191.93 5485.59,5192.79 5486.21,5193.76 5487.16,5195.98 5487.74,5198.35 5488.01,5200.67 5500.67,5188.01 5498.35,5187.74 5495.98,5187.16 5493.76,5186.21 5492.79,5185.59
  region net PAD15: 5298.59,4790 5298.59,4800 5299.71,4800.09 5300.84,4800.34 5303.07,4801.23 5305.17,4802.5 5306.99,4803.95 5306.99,4786.05 5305.17,4787.5 5303.07,4788.77 5300.84,4789.66 5299.71,4789.91
  region net PAD16: 5471.93,4474.86 5464.86,4481.93 5465.59,4482.79 5466.21,4483.76 5467.16,4485.98 5467.74,4488.35 5468.01,4490.67 5480.67,4478.01 5478.35,4477.74 5475.98,4477.16 5473.76,4476.21 5472.79,4475.59
  region net OUT: 4489.85,4917.01 4489.85,4927.01 4490.97,4927.1 4492.1,4927.35 4494.33,4928.24 4496.42,4929.51 4498.25,4930.96 4498.25,4913.06 4496.42,4914.51 4494.33,4915.77 4492.1,4916.67 4490.97,4916.92
  region net +5V: 4051.41,5300 4051.41,5290 4050.29,5289.91 4049.16,5289.66 4046.93,5288.77 4044.83,5287.5 4043.01,5286.05 4043.01,5303.95 4044.83,5302.5 4046.93,5301.23 4049.16,5300.34 4050.29,5300.09
  region net +5V: 4456.93,5299.86 4449.86,5306.93 4450.59,5307.79 4451.21,5308.76 4452.16,5310.98 4452.74,5313.35 4453.01,5315.67 4465.67,5303.01 4463.35,5302.74 4460.98,5302.16 4458.76,5301.21 4457.79,5300.59
  region net +5V: 4481.41,5320 4481.41,5310 4480.29,5309.91 4479.16,5309.66 4476.93,5308.77 4474.83,5307.5 4473.01,5306.05 4473.01,5323.95 4474.83,5322.5 4476.93,5321.23 4479.16,5320.34 4480.29,5320.09
  region net +5V: 4794.86,5278.07 4801.93,5285.14 4802.79,5284.41 4803.76,5283.79 4805.98,5282.84 4808.35,5282.26 4810.67,5281.99 4798.01,5269.33 4797.74,5271.65 4797.16,5274.02 4796.21,5276.24 4795.59,5277.21
  region net +5V: 4815,5253.59 4805,5253.59 4804.91,5254.71 4804.66,5255.84 4803.77,5258.07 4802.5,5260.17 4801.05,5261.99 4818.95,5261.99 4817.5,5260.17 4816.23,5258.07 4815.34,5255.84 4815.09,5254.71
  region net +5V: 4753.07,5055.14 4760.14,5048.07 4759.41,5047.21 4758.79,5046.24 4757.84,5044.02 4757.26,5041.65 4756.99,5039.33 4744.33,5051.99 4746.65,5052.26 4749.02,5052.84 4751.24,5053.79 4752.21,5054.41
  region net +5V: 4940.14,4856.93 4933.07,4849.86 4932.21,4850.59 4931.24,4851.21 4929.02,4852.16 4926.65,4852.74 4924.33,4853.01 4936.99,4865.67 4937.26,4863.35 4937.84,4860.98 4938.79,4858.76 4939.41,4857.79
  region net +5V: 5114.67,4516.5 5120.43,4524.89 5121.28,4524.16 5122.29,4523.54 5124.6,4522.61 5127.08,4522.1 5129.42,4521.99 5118.14,4508.09 5117.7,4510.35 5117.02,4512.61 5116.03,4514.71
  region net +5V: 4150,4848.59 4140,4848.59 4139.91,4849.71 4139.66,4850.84 4138.77,4853.07 4137.5,4855.17 4136.05,4856.99 4153.95,4856.99 4152.5,4855.17 4151.23,4853.07 4150.34,4850.84 4150.09,4849.71
  region net +5V: 4349.86,4478.07 4356.93,4485.14 4357.79,4484.41 4358.76,4483.79 4360.98,4482.84 4363.35,4482.26 4365.67,4481.99 4353.01,4469.33 4352.74,4471.65 4352.16,4474.02 4351.21,4476.24 4350.59,4477.21
  region net +5V: 4373.07,4485.14 4380.14,4478.07 4379.41,4477.21 4378.79,4476.24 4377.84,4474.02 4377.26,4471.65 4376.99,4469.33 4364.33,4481.99 4366.65,4482.26 4369.02,4482.84 4371.24,4483.79 4372.21,4484.41
  region net +5V: 4650.14,4561.93 4643.07,4554.86 4642.21,4555.59 4641.24,4556.21 4639.02,4557.16 4636.65,4557.74 4634.33,4558.01 4646.99,4570.67 4647.26,4568.35 4647.84,4565.98 4648.79,4563.76 4649.41,4562.79
  region net +5V: 4618.59,4565 4618.59,4575 4619.71,4575.09 4620.84,4575.34 4623.07,4576.23 4625.17,4577.5 4626.99,4578.95 4626.99,4561.05 4625.17,4562.5 4623.07,4563.77 4620.84,4564.66 4619.71,4564.91
  region net +5V: 4965.43,4702.21 4965.12,4672.02 4947.91,4640.84 cw(c4969.12,4619.62) 4990.33,4640.84 4996.65,4648.66 cw(c5047.86,4699.88) 4975.43,4699.88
